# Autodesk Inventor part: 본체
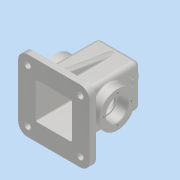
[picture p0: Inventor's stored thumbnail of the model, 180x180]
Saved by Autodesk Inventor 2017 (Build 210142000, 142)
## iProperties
Part Number: 본체
Material: 알루미늄 6061
Document SubType Name: Modeling
Designer: MRC
Density: 2.7 g/cm^3
Appearance: 알루미늄 - 평지
Mass: 753.527 g
Surface Area: 863.802 cm^2
Volume: 279.084 cm^3
Author: MRC
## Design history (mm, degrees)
sketch "스케치1"
  geometry: L1 (-34, -34)-(34, -34); L2 (34, -34)-(34, 34); L3 (34, 34)-(-34, 34); L4 (-34, 34)-(-34, -34); L5 (-34, -34)-(34, 34); L6 (34, -34)-(-34, 34); 1 further point
  constraints: 12 end point, 2 midpoint, 2 parallel, 1 horizontal, 1 perpendicular
  dimensions: "d0" = 68 distance of L3.end L2.end; "d1" = 68 distance of L2.end L1.end
extrude "돌출1" new body sketch "스케치1" distance "d2" = 53; taper "d4" = 0 deg; dims "d3" = 52, "d5" = 0
fillet "모깎기1" dims "d6" = 8
fillet "모깎기2" dims "d7" = 8
feature "쉘1" dims "d8" = 5
node "작업 평면1"
sketch "스케치2"
  geometry: C1 r 28.5 at (0, 0); 1 further point
  constraints: 1 centre point, 1 coincident
  dimensions: "d10" = 57 diameter of C1
extrude "돌출2" join sketch "스케치2" stored distance "d11" = 53; taper "d12" = 0 deg
fillet "모깎기3" dims "d13" = 3
hole "구멍1" diameter "d16" = 30; stored, may be unused: countersink angle "d20" = 90 deg, drill point angle "d22" = 118 deg; dims "d14" = 10, "d15" = 10, "d17" = 6, "d18" = 35, "d19" = 17, "d21" = 8
sketch "스케치3"
  geometry: C1 r 17.5 at (0, 0) reference; 1 further point
  constraints: 1 vertical alignment
  dimensions: "d23" = 22 distance of point (0, 22) C1.centre
hole "구멍2" sketch "스케치3" at (0, 22) diameter "d24" = 3.242; stored, may be unused: countersink angle "d28" = 90 deg, drill point angle "d30" = 118 deg; dims "d25" = 8, "d26" = 35, "d27" = 17, "d29" = 10
fillet "모깎기4" dims "d34" = 3
sketch "스케치4"
  geometry: C1 r 20 at (0, 0); 1 further point
  constraints: 1 centre point, 1 coincident
  dimensions: "d35" = 40 diameter of C1
extrude "돌출3" join sketch "스케치4" distance "d36" = 10; taper "d37" = 0 deg
hole "구멍3" diameter "d40" = 22.835; stored, may be unused: countersink angle "d44" = 90 deg, drill point angle "d46" = 118 deg; dims "d38" = 10, "d39" = 10, "d41" = 50, "d42" = 35, "d43" = 17, "d45" = 59.3
feature "면 기울기1" dims angle "d47" = 8 deg
sketch "스케치5"
  geometry: L1 (-26, -34)-(26, -34) reference; L2 (34, -26)-(34, 26) reference; L3 (26, 34)-(-26, 34) reference; L4 (-34, 26)-(-34, -26) reference; L5 (-57, 57)-(57, 57); L6 (57, 57)-(57, -57); L7 (57, -57)-(-57, -57); L8 (-57, -57)-(-57, 57); L9 (-57, 57)-(57, -57); L10 (57, 57)-(-57, -57); A1 r 8 centre (-26, -26) between (-34, -26) and (-26, -34) reference; A2 r 8 centre (26, -26) between (26, -34) and (34, -26) reference; A3 r 8 centre (26, 26) between (34, 26) and (26, 34) reference; A4 r 8 centre (-26, 26) between (-26, 34) and (-34, 26) reference; 1 further point
  constraints: 12 end point, 2 midpoint, 2 parallel, 1 horizontal, 1 perpendicular
  dimensions: "d48" = 114 distance of L6.end L7.end; "d49" = 114 distance of L5.end L6.end
extrude "돌출4" join sketch "스케치5" distance "d50" = 10; taper "d51" = 0 deg
fillet "모깎기5" dims "d52" = 15
sketch "스케치6"
  geometry: A1 r 15 centre (42, 42) between (57, 42) and (42, 57) reference; A2 r 15 centre (-42, 42) between (-42, 57) and (-57, 42) reference; A3 r 15 centre (-42, -42) between (-57, -42) and (-42, -57) reference; A4 r 15 centre (42, -42) between (42, -57) and (57, -42) reference; 5 further points
  constraints: 4 coincident
hole "구멍4" sketch "스케치6" at (-42, 42), (42, 42), (42, -42), (-42, -42) diameter "d53" = 10; stored, may be unused: countersink angle "d57" = 90 deg, drill point angle "d59" = 118 deg; dims "d54" = 50, "d55" = 18, "d56" = 2, "d58" = 59.3
sketch "스케치7"
  geometry: L1 (-29.986, -46.882)-(-42, -49); L2 (-42, -42)-(-42, -57) reference; L3 (-42, -57)-(-52, -57) reference; 1 further point
  constraints: 2 end point, 1 point on line
  dimensions: "d60" = 8 distance of L1.end L2.end; "d61" = 10 deg angle of L1 L3
feature "리브1" sketch "스케치7" dims "d62" = 1, "d63" = 10, "d64" = 0, "d65" = 0, "d66" = 1, "d67" = 1
fillet "모깎기6" dims "d68" = 3
fillet "모깎기7" dims "d69" = 3
fillet "모깎기8" dims "d70" = 3
fillet "모깎기9" dims "d71" = 0.3
chamfer "모따기1" distance "d72" = 1; stored, may be unused: second distance "d73" = 2, angle "d74" = 45 deg
chamfer "모따기2" distance "d75" = 1; stored, may be unused: second distance "d76" = 2, angle "d77" = 45 deg
fillet "모깎기10" dims "d78" = 3
node "작업 평면2"
sketch "스케치8"
  geometry: L1 (45, 34)-(-39, 34) reference; L2 (63, -20)-(63, 20) reference; 2 further points
  constraints: 1 other
  dimensions: "d80" = 34 distance from line of point (38, 0) L1; "d81" = 25 distance from line of point (38, 0) L2
feature "엠보싱1" sketch "스케치8" dims "d0" = 68, "d1" = 68, "d82" = 0.5, "d83" = 0
node "솔리드1"
pattern_circular "원형 패턴1" dims angle "d32" = 360 deg
mirror "미러1"
mirror "미러2"
other parameters: "d9" = 49, "d79" = 59
